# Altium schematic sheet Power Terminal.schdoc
size 138 x 187 mm
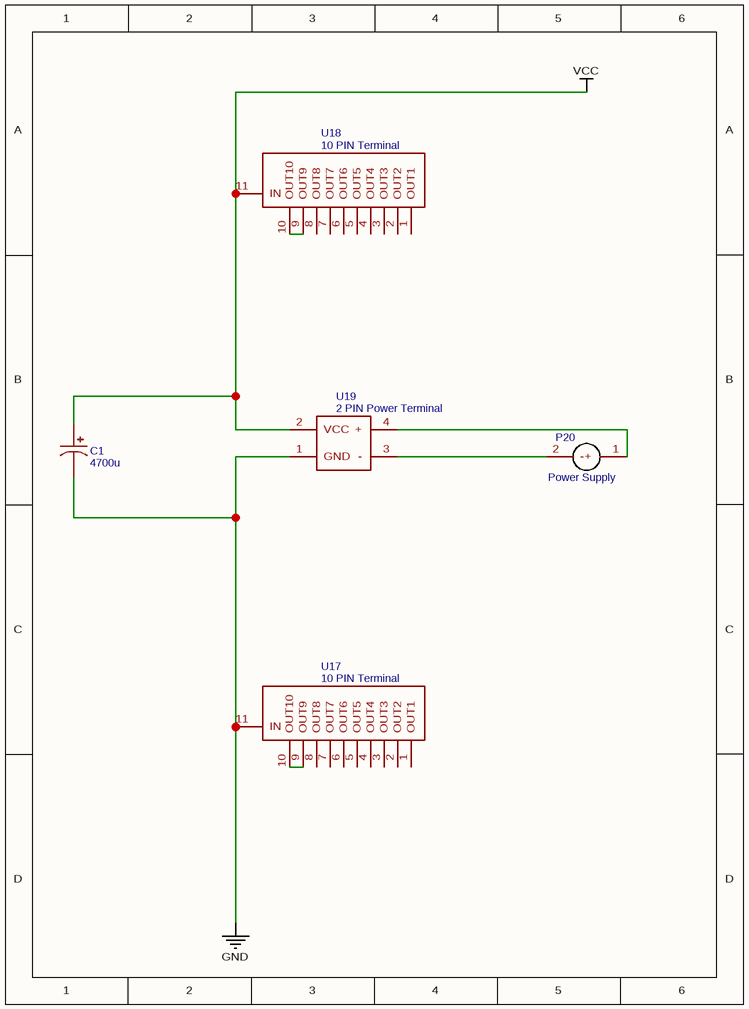
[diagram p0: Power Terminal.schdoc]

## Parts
C1  4700u  [CASE-A_3216]
P20  Power Supply
U17  10 PIN Terminal
U18  10 PIN Terminal
U19  2 PIN Power Terminal

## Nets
GND: C1.2 U17.11(IN) U19.1(GND)
VCC: C1.1 U18.11(IN) U19.2(VCC)
NetP20_1: P20.1(+) U19.4(+)
NetP20_2: P20.2(-) U19.3(-)
NetU17_9: U17.9(OUT9) U17.10(OUT10)
NetU18_9: U18.9(OUT9) U18.10(OUT10)

Not connected (* = marked no-connect by the designer): U17 1(OUT1) 2(OUT2) 3(OUT3) 4(OUT4) 5(OUT5) 6(OUT6) 7(OUT7) 8(OUT8); U18 1(OUT1) 2(OUT2) 3(OUT3) 4(OUT4) 5(OUT5) 6(OUT6) 7(OUT7) 8(OUT8)

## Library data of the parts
C1 = 4700u: nameAlias: Value(F); Contributor: LCEDA_Lib
P20 = Power Supply: Contributor: vinconloren
U17 U18 = 10 PIN Terminal: Contributor: vinconloren
U19 = 2 PIN Power Terminal: Contributor: vinconloren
